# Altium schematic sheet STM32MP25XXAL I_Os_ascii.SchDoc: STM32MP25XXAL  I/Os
size A3; Date: Not used; ApprovedBy: Not used; CheckedBy: Not used; Author: Not used; CompanyName: STMicroelectronics; DrawnBy: Not used; Engineer: Not used; Organization: Not used; Address1: Not used; Address2: Not used; Address3: Not used; Address4: Not used; DocumentNumber: 3; Revision: Not used; SheetNumber: 3; SheetTotal: 7
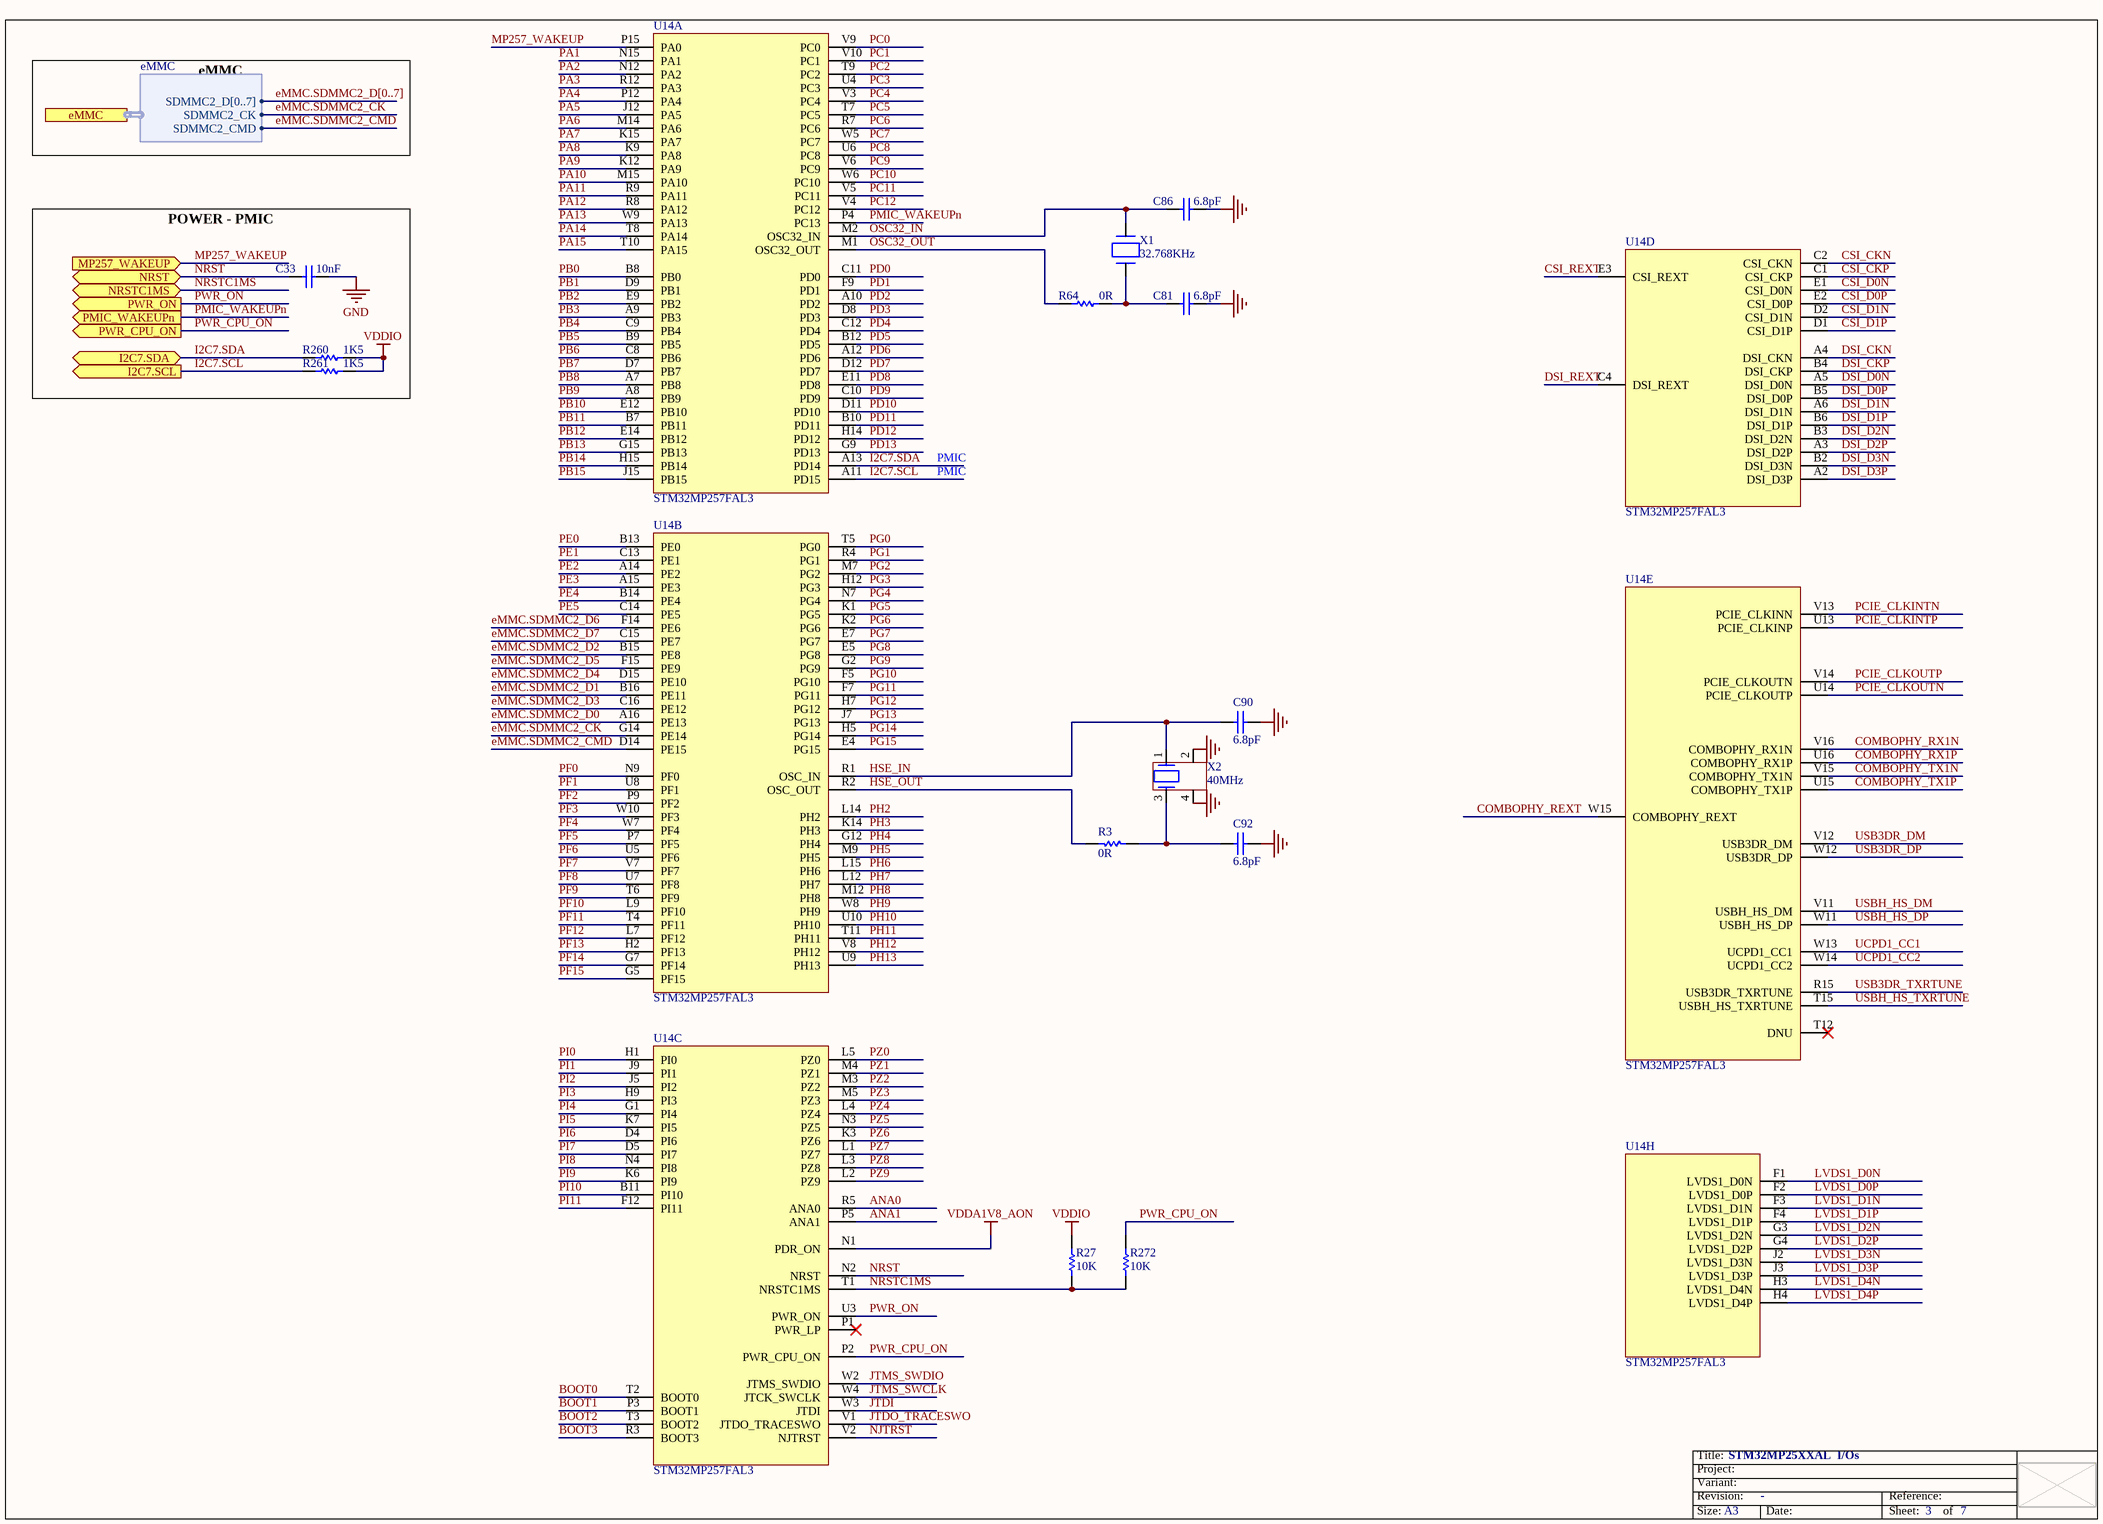
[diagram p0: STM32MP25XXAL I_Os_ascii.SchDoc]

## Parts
C33  value 10nF  [C0402]  (hidden comment: Capacitor)
C81  value 6.8pF  [C0402]  (hidden comment: Capacitor)
C86  value 6.8pF  [C0402]  (hidden comment: Capacitor)
C90  value 6.8pF  [C0402]  (hidden comment: Capacitor)
C92  value 6.8pF  [C0402]  (hidden comment: Capacitor)
R3  value 0R  [R0402]
R27  value 10K  [R0402]  (hidden comment: Resistor)
R64  value 0R  [R0402]
R260  value 1K5  [R0402]  (hidden comment: Resistor)
R261  value 1K5  [R0402]  (hidden comment: Resistor)
R272  value 10K  [R0402]  (hidden comment: Resistor)
U14  STM32MP257FAL3  [ICC_VFBGA361_10X10_P050]  (parts A,B,C,D,E,H of 8)
X1  value 32.768KHz  [CRY_NX2012SA_2P]  (hidden comment: XTAL_2_PINS)
X2  value 40MHz  [CRY_NX1612SA_4P]  (hidden comment: XTAL_4_PINS)

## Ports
eMMC (harness eMMC), I2C7.SCL (out), I2C7.SDA (bidir), MP257_WAKEUP (in), NRST (bidir), NRSTC1MS (bidir), PMIC_WAKEUPn (out), PWR_CPU_ON (out), PWR_ON (out)

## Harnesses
eMMC: SDMMC2_CK, SDMMC2_CMD, SDMMC2_D[0..7]

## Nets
GND: C33.1 C81.2 C86.2 C90.1 C92.2 X2.2 X2.4
VDDA1V8_AON: U14.N1(PDR_ON)
VDDIO: R27.2 R260.2 R261.2
ANA0: U14.R5(ANA0)
ANA1: U14.P5(ANA1)
BOOT0: U14.T2(BOOT0)
BOOT1: U14.P3(BOOT1)
BOOT2: U14.T3(BOOT2)
BOOT3: U14.R3(BOOT3)
COMBOPHY_REXT: U14.W15(COMBOPHY_REXT)
COMBOPHY_RX1N: U14.V16(COMBOPHY_RX1N)
COMBOPHY_RX1P: U14.U16(COMBOPHY_RX1P)
COMBOPHY_TX1N: U14.V15(COMBOPHY_TX1N)
COMBOPHY_TX1P: U14.U15(COMBOPHY_TX1P)
CSI_CKN: U14.C2(CSI_CKN)
CSI_CKP: U14.C1(CSI_CKP)
CSI_D0N: U14.E1(CSI_D0N)
CSI_D0P: U14.E2(CSI_D0P)
CSI_D1N: U14.D2(CSI_D1N)
CSI_D1P: U14.D1(CSI_D1P)
CSI_REXT: U14.E3(CSI_REXT)
DSI_CKN: U14.A4(DSI_CKN)
DSI_CKP: U14.B4(DSI_CKP)
DSI_D0N: U14.A5(DSI_D0N)
DSI_D0P: U14.B5(DSI_D0P)
DSI_D1N: U14.A6(DSI_D1N)
DSI_D1P: U14.B6(DSI_D1P)
DSI_D2N: U14.B3(DSI_D2N)
DSI_D2P: U14.A3(DSI_D2P)
DSI_D3N: U14.B2(DSI_D3N)
DSI_D3P: U14.A2(DSI_D3P)
DSI_REXT: U14.C4(DSI_REXT)
eMMC.SDMMC2_CK: U14.G14(PE14) ; port eMMC.SDMMC2_CK
eMMC.SDMMC2_CMD: U14.D14(PE15) ; port eMMC.SDMMC2_CMD
eMMC.SDMMC2_D0: U14.A16(PE13)
eMMC.SDMMC2_D1: U14.B16(PE11)
eMMC.SDMMC2_D2: U14.B15(PE8)
eMMC.SDMMC2_D3: U14.C16(PE12)
eMMC.SDMMC2_D4: U14.D15(PE10)
eMMC.SDMMC2_D5: U14.F15(PE9)
eMMC.SDMMC2_D6: U14.F14(PE6)
eMMC.SDMMC2_D7: U14.C15(PE7)
HSE_IN: C90.2 U14.R1(OSC_IN) X2.1
HSE_OUT: R3.2 U14.R2(OSC_OUT)
I2C7.SCL: R261.1 U14.A11(PD15) ; port I2C7.SCL
I2C7.SDA: R260.1 U14.A13(PD14) ; port I2C7.SDA
JTDI: U14.W3(JTDI)
JTDO_TRACESWO: U14.V1(JTDO_TRACESWO)
JTMS_SWCLK: U14.W4(JTCK_SWCLK)
JTMS_SWDIO: U14.W2(JTMS_SWDIO)
LVDS1_D0N: U14.F1(LVDS1_D0N)
LVDS1_D0P: U14.F2(LVDS1_D0P)
LVDS1_D1N: U14.F3(LVDS1_D1N)
LVDS1_D1P: U14.F4(LVDS1_D1P)
LVDS1_D2N: U14.G3(LVDS1_D2N)
LVDS1_D2P: U14.G4(LVDS1_D2P)
LVDS1_D3N: U14.J2(LVDS1_D3N)
LVDS1_D3P: U14.J3(LVDS1_D3P)
LVDS1_D4N: U14.H3(LVDS1_D4N)
LVDS1_D4P: U14.H4(LVDS1_D4P)
MP257_WAKEUP: U14.P15(PA0) ; port MP257_WAKEUP
NJTRST: U14.V2(NJTRST)
NRST: C33.2 U14.N2(NRST) ; port NRST
NRSTC1MS: R27.1 R272.1 U14.T1(NRSTC1MS) ; port NRSTC1MS
OSC32_IN: C86.1 U14.M2(OSC32_IN) X1.2(X2)
OSC32_OUT: R64.1 U14.M1(OSC32_OUT)
PA1: U14.N15(PA1)
PA2: U14.N12(PA2)
PA3: U14.R12(PA3)
PA4: U14.P12(PA4)
PA5: U14.J12(PA5)
PA6: U14.M14(PA6)
PA7: U14.K15(PA7)
PA8: U14.K9(PA8)
PA9: U14.K12(PA9)
PA10: U14.M15(PA10)
PA11: U14.R9(PA11)
PA12: U14.R8(PA12)
PA13: U14.W9(PA13)
PA14: U14.T8(PA14)
PA15: U14.T10(PA15)
PB0: U14.B8(PB0)
PB1: U14.D9(PB1)
PB2: U14.E9(PB2)
PB3: U14.A9(PB3)
PB4: U14.C9(PB4)
PB5: U14.B9(PB5)
PB6: U14.C8(PB6)
PB7: U14.D7(PB7)
PB8: U14.A7(PB8)
PB9: U14.A8(PB9)
PB10: U14.E12(PB10)
PB11: U14.B7(PB11)
PB12: U14.E14(PB12)
PB13: U14.G15(PB13)
PB14: U14.H15(PB14)
PB15: U14.J15(PB15)
PC0: U14.V9(PC0)
PC1: U14.V10(PC1)
PC2: U14.T9(PC2)
PC3: U14.U4(PC3)
PC4: U14.V3(PC4)
PC5: U14.T7(PC5)
PC6: U14.R7(PC6)
PC7: U14.W5(PC7)
PC8: U14.U6(PC8)
PC9: U14.V6(PC9)
PC10: U14.W6(PC10)
PC11: U14.V5(PC11)
PC12: U14.V4(PC12)
PCIE_CLKINTN: U14.V13(PCIE_CLKINN)
PCIE_CLKINTP: U14.U13(PCIE_CLKINP)
PCIE_CLKOUTN: U14.U14(PCIE_CLKOUTP)
PCIE_CLKOUTP: U14.V14(PCIE_CLKOUTN)
PD0: U14.C11(PD0)
PD1: U14.F9(PD1)
PD2: U14.A10(PD2)
PD3: U14.D8(PD3)
PD4: U14.C12(PD4)
PD5: U14.B12(PD5)
PD6: U14.A12(PD6)
PD7: U14.D12(PD7)
PD8: U14.E11(PD8)
PD9: U14.C10(PD9)
PD10: U14.D11(PD10)
PD11: U14.B10(PD11)
PD12: U14.H14(PD12)
PD13: U14.G9(PD13)
PE0: U14.B13(PE0)
PE1: U14.C13(PE1)
PE2: U14.A14(PE2)
PE3: U14.A15(PE3)
PE4: U14.B14(PE4)
PE5: U14.C14(PE5)
PF0: U14.N9(PF0)
PF1: U14.U8(PF1)
PF2: U14.P9(PF2)
PF3: U14.W10(PF3)
PF4: U14.W7(PF4)
PF5: U14.P7(PF5)
PF6: U14.U5(PF6)
PF7: U14.V7(PF7)
PF8: U14.U7(PF8)
PF9: U14.T6(PF9)
PF10: U14.L9(PF10)
PF11: U14.T4(PF11)
PF12: U14.L7(PF12)
PF13: U14.H2(PF13)
PF14: U14.G7(PF14)
PF15: U14.G5(PF15)
PG0: U14.T5(PG0)
PG1: U14.R4(PG1)
PG2: U14.M7(PG2)
PG3: U14.H12(PG3)
PG4: U14.N7(PG4)
PG5: U14.K1(PG5)
PG6: U14.K2(PG6)
PG7: U14.E7(PG7)
PG8: U14.E5(PG8)
PG9: U14.G2(PG9)
PG10: U14.F5(PG10)
PG11: U14.F7(PG11)
PG12: U14.H7(PG12)
PG13: U14.J7(PG13)
PG14: U14.H5(PG14)
PG15: U14.E4(PG15)
PH2: U14.L14(PH2)
PH3: U14.K14(PH3)
PH4: U14.G12(PH4)
PH5: U14.M9(PH5)
PH6: U14.L15(PH6)
PH7: U14.L12(PH7)
PH8: U14.M12(PH8)
PH9: U14.W8(PH9)
PH10: U14.U10(PH10)
PH11: U14.T11(PH11)
PH12: U14.V8(PH12)
PH13: U14.U9(PH13)
PI0: U14.H1(PI0)
PI1: U14.J9(PI1)
PI2: U14.J5(PI2)
PI3: U14.H9(PI3)
PI4: U14.G1(PI4)
PI5: U14.K7(PI5)
PI6: U14.D4(PI6)
PI7: U14.D5(PI7)
PI8: U14.N4(PI8)
PI9: U14.K6(PI9)
PI10: U14.B11(PI10)
PI11: U14.F12(PI11)
PMIC_WAKEUPn: U14.P4(PC13) ; port PMIC_WAKEUPn
PWR_CPU_ON: R272.2 U14.P2(PWR_CPU_ON) ; port PWR_CPU_ON
PWR_ON: U14.U3(PWR_ON) ; port PWR_ON
PZ0: U14.L5(PZ0)
PZ1: U14.M4(PZ1)
PZ2: U14.M3(PZ2)
PZ3: U14.M5(PZ3)
PZ4: U14.L4(PZ4)
PZ5: U14.N3(PZ5)
PZ6: U14.K3(PZ6)
PZ7: U14.L1(PZ7)
PZ8: U14.L3(PZ8)
PZ9: U14.L2(PZ9)
UCPD1_CC1: U14.W13(UCPD1_CC1)
UCPD1_CC2: U14.W14(UCPD1_CC2)
USB3DR_DM: U14.V12(USB3DR_DM)
USB3DR_DP: U14.W12(USB3DR_DP)
USB3DR_TXRTUNE: U14.R15(USB3DR_TXRTUNE)
USBH_HS_DM: U14.V11(USBH_HS_DM)
USBH_HS_DP: U14.W11(USBH_HS_DP)
USBH_HS_TXRTUNE: U14.T15(USBH_HS_TXRTUNE)
NetC81_1: C81.1 R64.2 X1.1(X1)
NetC92_1: C92.1 R3.1 X2.3

Not connected (* = marked no-connect by the designer): U14 P1(PWR_LP)* T12(DNU)*

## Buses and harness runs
bus eMMC.SDMMC2_D[0..7]

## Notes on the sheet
- eMMC
- POWER - PMIC
- PMIC

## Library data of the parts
C33 = MCD-00011: Capacitor, MLCC, 10nF, 16V, X7R, 10%, 0402, T=0.5mm; Manufacturer_Part_Number: CC0402KRX7R7BB103; Manufacturer: YAGEO; Provided_By: SUBCO; Initial_Board_Reference: MB1274
C81 C86 = MCD-00674: Capacitor, MLCC, 6.8pF, 50V, NPO, +-0.25pF, 0402, T=0.5mm; Manufacturer_Part_Number: CC0402CRNPO9BN6R8; Manufacturer: YAGEO; Part_Preference: Recommended; Provided_By: SUBCO; Initial_Board_Reference: MB1319; Path: ws/MCD_ApplicationBoards/Lists/MCDPARTSdatabase; Item Type: Item; Component_Country_Of_Origin: China; ID: 3068; ShowFields: YES
C90 C92 = MCD-00674: Capacitor, MLCC, 6.8pF, 50V, NPO, +-0.25pF, 0402, T=0.5mm; Manufacturer_Part_Number: CC0402CRNPO9BN6R8; Manufacturer: YAGEO; Part_Preference: Recommended; Provided_By: SUBCO; Initial_Board_Reference: MB1319; Component_Country_Of_Origin: China; ID: 3068; ShowFields: YES
R3 R64 = MCD-00052: Resistor,0R,0402,5%,1/16W; Manufacturer_Part_Number: RC0402JR-070RL; Manufacturer: YAGEO; Part_Preference: Recommended; Provided_By: SUBCO; Initial_Board_Reference: mb1274; Order_Code_RS: 618-5804; Component_Country_Of_Origin: China; ID: 2540; ShowFields: YES
R27 R272 = MCD-00053: Resistor,10K,0402,1%,1/16W; BMS_Part_Number: 9131590; Part_Preference: Recommended; Manufacturer: YAGEO; Manufacturer_Part_Number: RC0402FR-0710KL; Component_Country_Of_Origin: China; ID: 2539; ShowFields: YES
R260 R261 = MCD-00068: Resistor,1K5,0402,1%,1/16W; Part_Preference: Recommended; Manufacturer: YAGEO; Manufacturer_Part_Number: RC0402FR-071K5L; Component_Country_Of_Origin: China; ID: 2524; ShowFields: YES
U14 = MCD-03768: MPU, dual core ARM cortex-A35 64-bit + M33 32-bit, 808KB SRAM, With Crypto; Part_Type: IC; Part_Preference: Recommended; Manufacturer: STMICROELECTRONICS; Component_Country_Of_Origin: Unknown; ShowFields: YES; ID: 5884
X1 = MCD-01479: Crystal, 32.768kHz, 6pF, +/-20ppm, 80K, 2.05x1.2mm; BMS_Part_Number: 9157049; Part_Type: Crystal_Osc; Part_Preference: Recommended; Manufacturer: NDK; Manufacturer_Part_Number: NX2012SA-32.768KHZ-EXS00A-MU00527; Component_Country_Of_Origin: Unknown; ShowFields: YES; ID: 3579
X2 = MCD-02344: Crystal, 40MHz, 6pF, +/-20ppm, 80R, 1.6x1.2mm; Part_Type: Crystal_Osc; Part_Preference: Recommended; Manufacturer: NDK; Manufacturer_Part_Number: NX1612SA-40MHZ-EXS00A-CS13836; Component_Country_Of_Origin: Unknown; ShowFields: YES; ID: 4450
